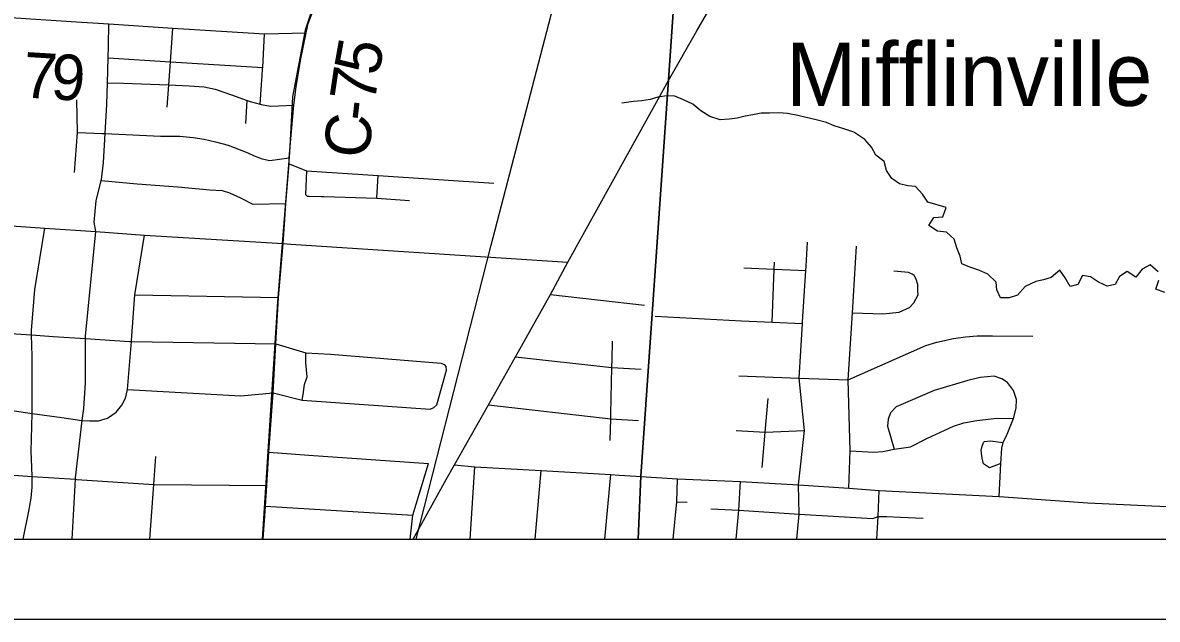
# Model space of a CAD drawing. Extents: x 0 to 34, y 0 to 22.
# Drawn here: x 2.735 to 4.152, y 14 to 14.745 of the extents above; entities that cross this region are included whole.
import ezdxf

# ---------------------------------------------------------------- set-up
doc = ezdxf.new("R2010")
doc.units = 0
for name, color, linetype in [('GM_X_City_Street', 7, 'Continuous'), ('GM_X_Corporation', 7, 'Continuous'), ('GM_X_County_Road', 7, 'Continuous'), ('GM_X_County_Road_Text', 7, 'Continuous'), ('GM_X_Minor_River', 7, 'Continuous'), ('GM_X_Rail_Line', 7, 'Continuous'), ('GM_X_State_Route', 7, 'Continuous'), ('GM_X_Township_Road', 7, 'Continuous'), ('GM_X_Township_Road_Text', 7, 'Continuous'), ('GM_X_Unincorporated_Text', 7, 'Continuous'), ('SH_Data', 7, 'Continuous')]:
    doc.layers.add(name, color=color, linetype=linetype)

msp = doc.modelspace()

# ---------------------------------------------------------------- linework, layer by layer
at = {"layer": 'GM_X_City_Street'}
for p, q in [((2.8408, 14.6701), (2.8608, 14.6697)), ((2.8749, 14.4053), (3.0543, 14.4017)), ((3.5247, 14.3786), (3.6326, 14.3727)), ((3.0424, 14.2088), (3.0922, 14.2052)), ((3.0922, 14.2052), (3.2417, 14.1944)), ((3.2938, 14.1), (3.2995, 14.1903)), ((3.3747, 14.1), (3.3825, 14.1858)), ((3.462, 14.1), (3.4692, 14.1809)), ((3.038, 14.1411), (3.222, 14.1299))]:
    msp.add_line(p, q, dxfattribs=at)
for points in [[(2.7967, 14.1), (2.8006, 14.1749), (2.8007, 14.1765), (2.8092, 14.2484), (2.811, 14.2634), (2.8133, 14.2953), (2.8134, 14.3507), (2.8134, 14.3538), (2.826, 14.4843), (2.8241, 14.4958), (2.8267, 14.5227), (2.8329, 14.548), (2.8332, 14.5493), (2.8359, 14.5705), (2.838, 14.6066), (2.8401, 14.6431), (2.8408, 14.6701), (2.8416, 14.7011), (2.842, 14.7163), (2.8426, 14.7436)], [(2.8034, 14.608), (2.834, 14.6068), (2.838, 14.6066), (2.8462, 14.6063), (2.9069, 14.6034), (2.9311, 14.6032), (2.9478, 14.6017), (2.9614, 14.5995), (2.9757, 14.5965), (2.9916, 14.592), (3.0161, 14.5827)], [(2.8329, 14.548), (2.878, 14.544), (2.9284, 14.5401), (2.9687, 14.5363), (2.9838, 14.5356), (2.993, 14.5325), (3.007, 14.5264), (3.0222, 14.5184)], [(2.7356, 14.1), (2.7427, 14.1352), (2.7453, 14.1511), (2.7468, 14.1651), (2.7465, 14.1785), (2.7462, 14.1902), (2.7455, 14.2096), (2.7466, 14.2572), (2.7466, 14.2582), (2.7467, 14.3288), (2.746, 14.3551), (2.7459, 14.3607), (2.75, 14.4118), (2.7626, 14.4885)], [(2.8587, 14.2674), (2.8631, 14.276), (2.8656, 14.2869), (2.8706, 14.3469), (2.8708, 14.3483), (2.8749, 14.4053), (2.8868, 14.4799)], [(2.1, 14.3995), (2.1067, 14.398), (2.1726, 14.4043), (2.2275, 14.3899), (2.3099, 14.3848), (2.3256, 14.3837), (2.3332, 14.3832), (2.3726, 14.3805), (2.4367, 14.3761), (2.5522, 14.3683), (2.6221, 14.3636), (2.6798, 14.3596), (2.746, 14.3551), (2.7731, 14.3533), (2.8134, 14.3507), (2.8682, 14.3471), (2.8706, 14.3469), (3.0509, 14.3442), (3.0885, 14.3328), (3.1192, 14.331), (3.2575, 14.3197), (3.2613, 14.3182), (3.2636, 14.3155)], [(3.0839, 14.2738), (3.0853, 14.2806), (3.0868, 14.2933), (3.09, 14.3028), (3.0884, 14.3202), (3.0885, 14.3328)], [(3.2482, 14.2645), (3.2521, 14.2679), (3.264, 14.3113), (3.2636, 14.3155)], [(2.8656, 14.2869), (3.0073, 14.2792), (3.0475, 14.2828), (3.0839, 14.2738), (3.0959, 14.273), (3.2436, 14.2624), (3.2482, 14.2645)], [(2.5464, 14.2757), (2.6137, 14.2707), (2.6162, 14.2705), (2.6821, 14.2665), (2.6834, 14.2664), (2.7382, 14.2584), (2.7466, 14.2572), (2.7836, 14.252), (2.8086, 14.2484), (2.8092, 14.2484), (2.8184, 14.2479), (2.8203, 14.2477), (2.8294, 14.2479), (2.8409, 14.2514), (2.8517, 14.2588), (2.8587, 14.2674)], [(2.1, 14.2211), (2.158, 14.2231), (2.2105, 14.2135), (2.2692, 14.2102), (2.3135, 14.2077), (2.3146, 14.2076), (2.3515, 14.2055), (2.3609, 14.2049), (2.4258, 14.2004), (2.5416, 14.1925), (2.6129, 14.1876), (2.619, 14.1871), (2.6947, 14.182), (2.7465, 14.1785), (2.8006, 14.1749), (2.8024, 14.1748), (2.8986, 14.1683), (3.0397, 14.1672)], [(2.8937, 14.1), (2.8986, 14.1683), (2.9011, 14.2035)], [(3.2186, 14.1), (3.222, 14.1299), (3.2417, 14.1944)]]:
    msp.add_lwpolyline(points, dxfattribs=at)
at = {"layer": 'GM_X_Corporation'}
msp.add_lwpolyline([(2.1, 20.9), (2.1, 14.1), (6.2395, 14.1)], dxfattribs=at)
at = {"layer": 'GM_X_County_Road'}
for p, q in [((3.0696, 14.4686), (3.3388, 14.451)), ((3.3388, 14.451), (3.4157, 14.446)), ((3.4797, 14.1802), (3.5006, 14.1787)), ((3.7666, 14.1637), (3.8044, 14.161))]:
    msp.add_line(p, q, dxfattribs=at)
msp.add_lwpolyline([(2.1, 16.5143), (2.1, 14.1), (3.5033, 14.1), (3.5067, 14.1788), (3.5412, 14.6736), (3.5547, 14.8664), (3.6065, 15.7173), (3.6083, 15.7281), (3.6105, 15.7435), (3.6146, 15.8068), (3.6204, 15.8961), (3.634, 16.1053), (3.6418, 16.2257), (3.654, 16.4154), (3.6172, 16.4188), (3.4065, 16.4352), (3.1867, 16.4496), (3.1585, 16.4507), (3.0788, 16.4569), (2.884, 16.4676), (2.7034, 16.4752), (2.5328, 16.4826), (2.3641, 16.4932), (2.2435, 16.5033)], close=True, dxfattribs=at)
for points in [[(5.4989, 16.2977), (5.2615, 16.3089), (5.0301, 16.3238), (4.7825, 16.3404), (4.4809, 16.3594), (4.0961, 16.3837), (3.9805, 16.3916), (3.8512, 16.4005), (3.654, 16.4154), (3.6418, 16.2257), (3.634, 16.1053), (3.6204, 15.8961), (3.6146, 15.8068), (3.6105, 15.7435), (3.6083, 15.7281), (3.6065, 15.7173), (3.5547, 14.8664), (3.5412, 14.6736), (3.5067, 14.1788), (3.5033, 14.1), (8.2619, 14.1)], [(3.0621, 14.4992), (3.0635, 14.5192), (3.0677, 14.5689), (3.0677, 14.5764), (3.0735, 14.6423), (3.0765, 14.6649), (3.0818, 14.698), (3.0887, 14.7325), (3.0915, 14.7442), (3.1083, 14.7882), (3.1272, 14.8409), (3.1443, 14.8912), (3.214, 15.099), (3.2176, 15.1106)], [(2.1, 14.535), (2.1207, 14.5336), (2.1835, 14.5283), (2.201, 14.5274), (2.2437, 14.5243), (2.3085, 14.5201), (2.3421, 14.5175), (2.358, 14.5164), (2.3862, 14.5143), (2.4527, 14.5096), (2.5654, 14.5026), (2.6358, 14.4976), (2.6964, 14.4932), (2.7626, 14.4885), (2.826, 14.4843), (2.8868, 14.4799), (3.06, 14.4692), (3.0696, 14.4686)], [(3.0568, 14.4306), (3.06, 14.4692), (3.0621, 14.4992)], [(3.035, 14.1), (3.038, 14.1411), (3.0397, 14.1672), (3.0424, 14.2088), (3.0475, 14.2828), (3.0509, 14.3442), (3.0543, 14.4017), (3.0568, 14.4306)], [(3.2741, 14.1929), (3.2995, 14.1903), (3.3825, 14.1858), (3.4692, 14.1809), (3.4797, 14.1802)], [(3.5006, 14.1787), (3.5069, 14.1783), (3.5525, 14.1753), (3.6116, 14.1729)], [(3.6116, 14.1729), (3.6313, 14.1721), (3.7039, 14.1678), (3.7666, 14.1637)], [(3.8044, 14.161), (3.9542, 14.1532), (4.0651, 14.1455), (4.1448, 14.1418), (4.2237, 14.1384), (4.2365, 14.1377)]]:
    msp.add_lwpolyline(points, dxfattribs=at)
at = {"layer": 'GM_X_Minor_River'}
for points in [[(3.8881, 14.5141), (3.8654, 14.5211), (3.8587, 14.531), (3.85, 14.5406), (3.8402, 14.5415), (3.83, 14.5438), (3.8202, 14.5504), (3.8138, 14.5603), (3.8109, 14.5717), (3.8004, 14.5798), (3.7948, 14.5897), (3.7865, 14.5993), (3.7729, 14.6082), (3.7605, 14.6125), (3.7484, 14.6164), (3.7386, 14.6203), (3.7257, 14.6238), (3.7132, 14.6266), (3.703, 14.6293), (3.6898, 14.6317), (3.6792, 14.6326), (3.6674, 14.6323), (3.6572, 14.632), (3.6466, 14.6302), (3.6371, 14.6284), (3.6272, 14.6259), (3.6173, 14.6248), (3.6059, 14.6238), (3.5931, 14.6281), (3.5818, 14.635), (3.5716, 14.6435), (3.5603, 14.6489), (3.5494, 14.6532), (3.5391, 14.6537), (3.5281, 14.6519), (3.5186, 14.6493), (3.5076, 14.6475), (3.4978, 14.6465), (3.486, 14.645), (3.4833, 14.6447)], [(4.153, 14.4341), (4.1429, 14.4425), (4.133, 14.4373), (4.1249, 14.4271), (4.1144, 14.4345), (4.1045, 14.4281), (4.0991, 14.4183), (4.0892, 14.4161), (4.0786, 14.4211), (4.0685, 14.4277), (4.0586, 14.4293), (4.0524, 14.4183), (4.043, 14.4158), (4.0366, 14.4265), (4.0299, 14.436), (4.0192, 14.427), (4.0097, 14.4241), (4.0002, 14.4219), (3.9869, 14.4155), (3.9773, 14.405), (3.967, 14.4013), (3.956, 14.4014), (3.9516, 14.4113), (3.9505, 14.4212), (3.94, 14.4312), (3.9291, 14.4362), (3.9177, 14.4397), (3.9079, 14.444), (3.9057, 14.4535), (3.9016, 14.4638), (3.8983, 14.4748), (3.8885, 14.4833), (3.8772, 14.4849), (3.8663, 14.4919), (3.8728, 14.5017), (3.8838, 14.5027), (3.8881, 14.5141)], [(4.1611, 14.4082), (4.1502, 14.4121), (4.1537, 14.4235)]]:
    msp.add_lwpolyline(points, dxfattribs=at)
at = {"layer": 'GM_X_Rail_Line'}
for points in [[(3.7202, 17.4495), (3.6121, 15.7571), (3.5991, 15.7141), (3.5781, 15.6833), (3.3718, 15.4026), (3.2933, 15.2964), (3.27, 15.2612), (3.26, 15.2394), (3.2447, 15.1962), (3.2204, 15.1356), (3.1206, 14.8429), (3.107, 14.7951), (3.0878, 14.7358), (3.0717, 14.6527), (3.0679, 14.583), (3.0599, 14.4798), (3.0531, 14.3964), (3.0341, 14.1)], [(3.2263, 14.1), (3.3201, 14.4671), (3.4798, 15.0811), (3.5889, 15.5111), (3.6244, 15.6418), (3.9439, 16.2089), (4.0935, 16.4703), (4.1354, 16.5172), (4.1886, 16.568), (4.5538, 16.8382), (4.6413, 16.9169), (4.6831, 16.9702), (4.73, 17.0374), (4.7604, 17.097), (4.7896, 17.177), (4.8023, 17.2505), (4.8213, 17.366)]]:
    msp.add_lwpolyline(points, dxfattribs=at)
at = {"layer": 'GM_X_State_Route'}
for p, q in [((3.5769, 14.7351), (3.6569, 14.8747)), ((3.2223, 14.1), (3.2638, 14.1745))]:
    msp.add_line(p, q, dxfattribs=at)
for points in [[(3.4157, 14.446), (3.5414, 14.6731), (3.5769, 14.7351)], [(3.2638, 14.1745), (3.2741, 14.1929), (3.3165, 14.2678), (3.3504, 14.3277), (3.394, 14.4055), (3.4157, 14.446)]]:
    msp.add_lwpolyline(points, dxfattribs=at)
at = {"layer": 'GM_X_Township_Road'}
for p, q in [((3.0315, 14.6432), (3.0339, 14.6797)), ((2.8034, 14.608), (2.8026, 14.6488)), ((3.0136, 14.6192), (3.015, 14.6479)), ((2.7997, 14.5581), (2.8034, 14.608)), ((3.1773, 14.5258), (3.1788, 14.5541)), ((3.0222, 14.5184), (3.0635, 14.5192)), ((3.7032, 14.4362), (3.7129, 14.4358)), ((3.394, 14.4055), (3.5112, 14.3922)), ((3.6291, 14.304), (3.7044, 14.3011)), ((3.7044, 14.3011), (3.7659, 14.299)), ((3.4685, 14.2233), (3.4692, 14.2504)), ((3.5517, 14.1468), (3.5645, 14.1464)), ((3.8311, 14.1277), (3.8595, 14.1263))]:
    msp.add_line(p, q, dxfattribs=at)
for points in [[(2.6849, 14.7535), (2.6932, 14.753), (2.7199, 14.7515), (2.7954, 14.7466), (2.8426, 14.7436), (2.9224, 14.7384), (3.0367, 14.731), (3.0887, 14.7325)], [(2.9154, 14.6395), (2.9174, 14.6675), (2.9194, 14.6963), (2.9224, 14.7384)], [(3.0339, 14.6797), (3.0344, 14.687), (3.0346, 14.6892), (3.0367, 14.731)], [(2.8416, 14.7011), (2.9194, 14.6963), (3.0346, 14.6892)], [(2.8608, 14.6697), (2.9055, 14.6681), (2.9174, 14.6675), (2.9427, 14.6661), (2.9613, 14.6651), (2.9753, 14.6622), (2.9958, 14.6548), (3.015, 14.6479)], [(3.015, 14.6479), (3.0188, 14.6465), (3.0315, 14.6432)], [(3.0315, 14.6432), (3.0328, 14.6429), (3.0446, 14.6408), (3.0735, 14.6423)], [(3.0161, 14.5827), (3.0241, 14.5788), (3.0339, 14.5752), (3.0434, 14.5732), (3.0677, 14.5764)], [(3.0677, 14.5689), (3.0894, 14.5599), (3.1788, 14.5541), (3.3231, 14.5448)], [(3.0894, 14.5599), (3.0881, 14.5304), (3.09, 14.5285), (3.0926, 14.5284), (3.1078, 14.528)], [(3.1078, 14.528), (3.1109, 14.5279), (3.1773, 14.5258), (3.218, 14.523)], [(3.7129, 14.4358), (3.7133, 14.441), (3.7151, 14.4708)], [(3.7666, 14.1637), (3.7683, 14.2106), (3.7659, 14.299), (3.7711, 14.3826), (3.7763, 14.4658)], [(3.671, 14.371), (3.6735, 14.4373), (3.6738, 14.4462)], [(3.6353, 14.4388), (3.6735, 14.4373), (3.7032, 14.4362)], [(3.7087, 14.3694), (3.7089, 14.3717), (3.7129, 14.4358)], [(3.7711, 14.3826), (3.809, 14.3817), (3.8296, 14.3834), (3.8422, 14.3893), (3.8476, 14.3953), (3.853, 14.4051), (3.8527, 14.4108), (3.8528, 14.418), (3.8506, 14.4249), (3.848, 14.4295), (3.8458, 14.431), (3.8412, 14.433), (3.8226, 14.4348)], [(3.6326, 14.3727), (3.671, 14.371), (3.7087, 14.3694)], [(3.7039, 14.1678), (3.7113, 14.2359), (3.7044, 14.3011), (3.7087, 14.3694)], [(3.4707, 14.3144), (3.471, 14.3249), (3.4716, 14.3475)], [(3.7659, 14.299), (3.8629, 14.3419), (3.8766, 14.3463), (3.8972, 14.3506), (3.9124, 14.3526), (3.9269, 14.354), (3.9459, 14.3541), (3.9964, 14.3538)], [(3.3504, 14.3277), (3.4707, 14.3144), (3.5072, 14.3124)], [(3.4692, 14.2504), (3.4693, 14.2571), (3.4707, 14.3144)], [(3.9542, 14.1532), (3.9565, 14.1947), (3.9575, 14.2136), (3.9592, 14.2207), (3.9643, 14.2312), (3.9724, 14.2507), (3.9756, 14.2636), (3.9761, 14.2746), (3.9724, 14.2857), (3.9649, 14.2957), (3.9578, 14.3003), (3.9483, 14.3035), (3.9392, 14.3029), (3.9308, 14.3018), (3.9152, 14.2983), (3.8732, 14.2859), (3.8255, 14.2652), (3.8185, 14.2577), (3.8158, 14.2498), (3.8149, 14.2411), (3.8233, 14.2123)], [(3.6585, 14.1896), (3.6623, 14.2338), (3.666, 14.2757)], [(3.3165, 14.2678), (3.4692, 14.2504), (3.5038, 14.2482)], [(3.7683, 14.2106), (3.798, 14.2089), (3.8091, 14.2096), (3.8233, 14.2123), (3.8435, 14.2156), (3.8649, 14.2263), (3.8974, 14.2411), (3.9104, 14.2455), (3.9264, 14.2483), (3.9515, 14.251), (3.9724, 14.2507)], [(3.626, 14.2356), (3.6623, 14.2338), (3.7113, 14.2359)], [(3.9565, 14.1947), (3.9422, 14.1891), (3.9348, 14.1942), (3.933, 14.2011), (3.932, 14.211), (3.9332, 14.2161), (3.9348, 14.2208), (3.9362, 14.2221), (3.9432, 14.2231), (3.9592, 14.2207)], [(3.5472, 14.1), (3.5517, 14.1468), (3.5525, 14.1753)], [(3.626, 14.1), (3.6294, 14.1364), (3.6313, 14.1721)], [(3.7015, 14.1), (3.7047, 14.1314), (3.7039, 14.1678)], [(3.8017, 14.1), (3.8033, 14.1283), (3.8044, 14.161)], [(3.5942, 14.1381), (3.6294, 14.1364), (3.7047, 14.1314), (3.7965, 14.1257), (3.8033, 14.1283), (3.8123, 14.1285)], [(3.8123, 14.1285), (3.8141, 14.1285), (3.8311, 14.1277)]]:
    msp.add_lwpolyline(points, dxfattribs=at)
at = {"layer": 'SH_Data'}
for p, q in [((2.1, 14.1), (8.9, 14.1)), ((2, 14), (9, 14))]:
    msp.add_line(p, q, dxfattribs=at)

# ---------------------------------------------------------------- texts
at = {"layer": 'GM_X_County_Road_Text'}
for s, rotation, p in [('5', 79.7301, (3.1792, 14.6775)), ('7', 81.6123, (3.1742, 14.6433)), ('-', 83.2797, (3.1715, 14.6206)), ('C', 84.5943, (3.1672, 14.5745))]:
    msp.add_text(s, height=0.0568, rotation=rotation, dxfattribs=at).set_placement(p)
at = {"layer": 'GM_X_Township_Road_Text'}
for s, rotation, p in [('7', 356.5152, (2.7341, 14.6519)), ('9', 356.6213, (2.7691, 14.6497))]:
    msp.add_text(s, height=0.0568, rotation=rotation, dxfattribs=at).set_placement(p)
at = {"layer": 'GM_X_Unincorporated_Text'}
msp.add_text('Mifflinville', height=0.078977, rotation=0, dxfattribs=at).set_placement((3.688, 14.6412))

doc.saveas('drawing.dxf')
